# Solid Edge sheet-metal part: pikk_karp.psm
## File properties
Author: Mac
Template: Normal.psm
Last saved by: Mac
Revision: 4
Application: Solid Edge
Material: Aluminum, 1060
Face Style: Aluminum
Fill Style: ANSI38(Aluminum)
Virtual Style: Brushed aluminum pattern
Coef. of Thermal Exp: 2.3e-05
Thermal Conductivity: 221.0
Specific Heat: 920.0
Modulus of Elasticity: 68947570000.0
Poission's Ratio: 0.33
Yield Stress: 27579028.0
Ultimate Stress: 68947570.0
Elongation: 0.0
Density: 2712,000 kg/m^3
Accuracy: 0,990
Material Thickness: 0,06 mm
Bend Radius: 1,00 mm
Relief Width: 1,00 mm
Relief Length: 0,00 mm
Neutral Factor: 0,330
Minimum Arc Length: 0,10 mm
Deviational Tolerance: 0,10 mm
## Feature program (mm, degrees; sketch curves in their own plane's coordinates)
base contour flange "ContourFlange_1"
sheet metal cutout "unnamed SheetMetalCutout 1"
insert bend "InsertBend_2"  BendAngle = 90 deg
body pattern "unnamed BodyPattern 1"
pattern "unnamed Pattern 1"
break corner "unnamed BreakCorner 1"
sheet metal cutout "unnamed SheetMetalCutout 2"
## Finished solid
Body 1: solid body, 48 faces, 108 edges, 60 vertices.
  Faces by surface: plane 32, cylinder 12, spline 4
  Edges by curve: line 84, circle 16, ellipse 8
Bounding box of the edges (mm; curved faces can reach further): 2.130 x 33.680 x 0.800, from (-1.4298, 0.06, 0) to (0.7, 33.74, 0.8).
Cylindrical faces by radius (mm): R0.002 x5, R0.062 x5, R0.0865 x2
Planar faces by outward normal: +x 3, +y 5, +z 4, -x 6, -y 5, -z 3, oblique 6
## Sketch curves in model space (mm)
line (-0.638, 16.138, 0) -> (-0.638, 17.662, 0)
line (-25.762, 17.662, 0) -> (-25.762, 16.138, 0)
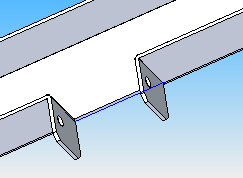
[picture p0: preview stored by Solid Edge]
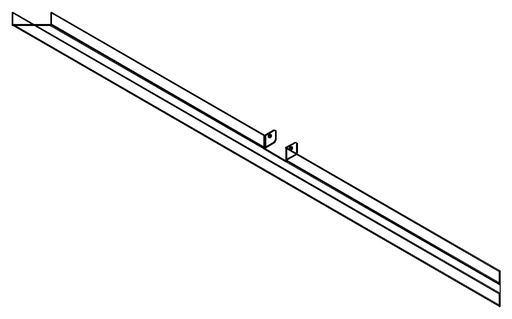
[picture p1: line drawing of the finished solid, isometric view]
